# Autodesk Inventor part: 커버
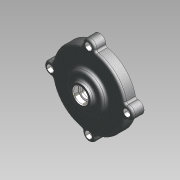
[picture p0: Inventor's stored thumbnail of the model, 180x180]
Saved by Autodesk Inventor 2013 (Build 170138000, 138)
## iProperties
Company: 한국ATC센터
Created: 2014-07
Part Number: 커버
Document SubType Name: 모델링
Designer: KYOUNG IL JANG
Material: 알루미늄 6061
Mass: 174.693 g
Surface Area: 278.607 cm^2
Volume: 72.5678 cm^3
Density: 2.40731 g/cm^3
변환 표준: STEP AP214IS
파일 이름: C:\Users\SeoGD\Desktop\?쒗뿕\而ㅻ쾭-1.stp
전처리기: Build: 253, Release: 2010 SP1 - Date: Wed 07/29/2009
전송 단위: 밀리미터
불확실성: 0.01
Author: KYOUNG IL JANG
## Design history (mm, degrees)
sketch "스케치1"
  geometry: L1 (0, 0)-(0, 26); L2 (50, 0)-(50, 15); L3 (50, 15)-(25, 15); L4 (25, 15)-(25, 21); L5 (25, 21)-(15, 21); L6 (15, 21)-(13.66, 26); L7 (13.66, 26)-(10, 26); L8 (50, 0)-(45, 0); L9 (45, 0)-(45, 10); L10 (45, 10)-(14.5, 10); L11 (14.5, 10)-(13.266, 3); L12 (13.266, 3)-(11, 3); L13 (11, 3)-(11, 16); L14 (11, 16)-(7.5, 16); L15 (7.5, 16)-(7.5, 19); L16 (7.5, 19)-(10, 19); L17 (10, 19)-(10, 26)
  constraints: 34 end point, 10 parallel, 2 perpendicular, 2 point on line, 1 vertical
  dimensions: "d11" = 100 diameter of L2 L1; "d12" = 22 diameter of L13 L1; "d13" = 90 diameter of L9 L1; "d14" = 15 distance between parallel lines of L3 L8; "d15" = 10 distance between parallel lines of L8 L10; "d16" = 29 diameter of L10.end L1; "d17" = 100 deg angle of L11 L10; "d18" = 7 distance between parallel lines of L12 L10; "d19" = 13 distance between parallel lines of L14 L12; "d20" = 3 distance between parallel lines of L16 L14; "d21" = 15 diameter of L15 L1; "d22" = 20 diameter of L17 L1; "d23" = 30 diameter of L5.end L1; "d24" = 6 distance between parallel lines of L5 L3; "d25" = 50 diameter of L4 L1; "d26" = 105 deg angle of L5 L6; "d50" = 26 distance of L1.start L1.end
revolve "회전1" sketch "스케치1" stored, may be unused: angle "d27" = 90 deg
sketch "스케치2" dims "d29" = 104
  geometry: A1 r 8.5 centre (0, 52) between (8.074, 49.344) and (-8.074, 49.344); A2 r 50 centre (0, 0) between (-8.074, 49.344) and (8.074, 49.344) reference; 2 further points
  constraints: 4 point on circle, 2 vertical alignment, 1 centre point, 1 coincident, 2 other
  dimensions: "d28" = 17 diameter of A1
extrude "돌출1" join sketch "스케치2" stored distance "d30" = 10; taper "d31" = 0 deg
fillet "모깎기3" dims "d32" = 3
fillet "모깎기4" dims "d45" = 3, "d46" = 0.2
chamfer "모따기1" distance "d47" = 1; stored, may be unused: second distance "d48" = 2, angle "d49" = 45 deg
hole "구멍2" diameter "d38" = 5.5; stored, may be unused: countersink angle "d42" = 90 deg, drill point angle "d44" = 118 deg; dims "d36" = 10, "d37" = 10, "d39" = 6, "d40" = 9.5, "d41" = 5.4, "d43" = 8
node "솔리드1"
node "솔리드 본체"
node "곡면 본체"
pattern_circular "원형 패턴1" dims angle "d34" = 360 deg
pattern_circular "원형 패턴2" dims angle "d52" = 360 deg
node "솔리드2"
